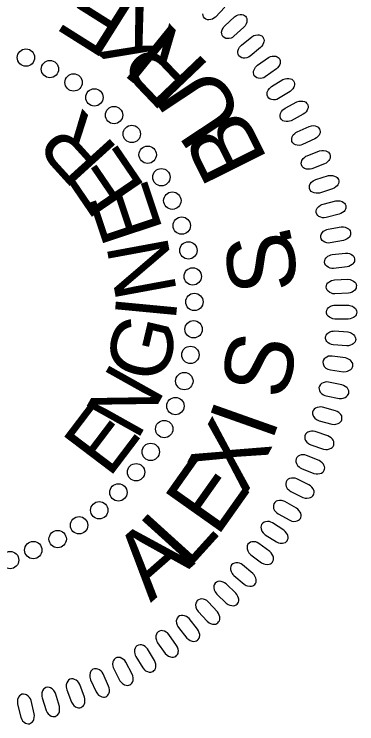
# Model space of a CAD drawing. Extents: x 474105 to 475385, y 502977 to 504774.
# Drawn here: x 474244.3 to 474275.9, y 504557.9 to 504623.4 of the extents above; entities that cross this region are included whole.
import ezdxf

# ---------------------------------------------------------------- set-up
doc = ezdxf.new("R2010")
doc.units = 0
doc.layers.add('Sheet PE Seal Cell', color=7, linetype='Continuous')

msp = doc.modelspace()

# ---------------------------------------------------------------- linework, layer by layer
at = {"layer": 'Sheet PE Seal Cell'}
msp.add_lwpolyline([(474263.704, 504624.083), (474262.838, 504623.172), (474262.704, 504623.065), (474262.575, 504622.996), (474262.4, 504622.943), (474262.223, 504622.919), (474262.097, 504622.93), (474261.943, 504622.995), (474261.821, 504623.084), (474261.741, 504623.216), (474261.7, 504623.326), (474261.677, 504623.485)], dxfattribs=at)
for points in [[(474263.705, 504622.369), (474264.609, 504623.198), (474264.796, 504623.318), (474264.933, 504623.375), (474265.134, 504623.407), (474265.281, 504623.409), (474265.416, 504623.381), (474265.516, 504623.33), (474265.606, 504623.261), (474265.667, 504623.165), (474265.726, 504623.057), (474265.753, 504622.94), (474265.75, 504622.795), (474265.732, 504622.697), (474265.667, 504622.546), (474265.575, 504622.38), (474265.473, 504622.256), (474264.552, 504621.401), (474264.412, 504621.303), (474264.278, 504621.242), (474264.1, 504621.2), (474263.922, 504621.188), (474263.797, 504621.206), (474263.647, 504621.281), (474263.531, 504621.378), (474263.46, 504621.515), (474263.426, 504621.626), (474263.413, 504621.787), (474263.457, 504621.989), (474263.544, 504622.161), (474263.619, 504622.27)], [(474265.246, 504620.589), (474266.201, 504621.36), (474266.394, 504621.469), (474266.536, 504621.516), (474266.739, 504621.535), (474266.885, 504621.529), (474267.018, 504621.492), (474267.115, 504621.436), (474267.201, 504621.36), (474267.255, 504621.261), (474267.307, 504621.149), (474267.327, 504621.03), (474267.315, 504620.886), (474267.29, 504620.789), (474267.216, 504620.643), (474267.114, 504620.483), (474267.004, 504620.366), (474266.031, 504619.571), (474265.885, 504619.481), (474265.749, 504619.429), (474265.568, 504619.398), (474265.389, 504619.397), (474265.266, 504619.423), (474265.12, 504619.507), (474265.011, 504619.612), (474264.948, 504619.753), (474264.921, 504619.865), (474264.918, 504620.027), (474264.976, 504620.226), (474265.073, 504620.392), (474265.155, 504620.496)], [(474266.724, 504618.727), (474267.726, 504619.436), (474267.926, 504619.533), (474268.07, 504619.571), (474268.273, 504619.578), (474268.419, 504619.562), (474268.549, 504619.516), (474268.642, 504619.454), (474268.723, 504619.374), (474268.771, 504619.272), (474268.816, 504619.156), (474268.828, 504619.037), (474268.807, 504618.894), (474268.777, 504618.798), (474268.694, 504618.657), (474268.582, 504618.504), (474268.465, 504618.394), (474267.444, 504617.661), (474267.293, 504617.581), (474267.152, 504617.537), (474266.971, 504617.518), (474266.792, 504617.528), (474266.67, 504617.562), (474266.531, 504617.655), (474266.428, 504617.766), (474266.375, 504617.91), (474266.354, 504618.025), (474266.362, 504618.186), (474266.431, 504618.382), (474266.539, 504618.541), (474266.627, 504618.64)], [(474268.021, 504616.76), (474269.065, 504617.405), (474269.27, 504617.489), (474269.417, 504617.518), (474269.62, 504617.512), (474269.764, 504617.487), (474269.891, 504617.433), (474269.98, 504617.366), (474270.056, 504617.28), (474270.098, 504617.175), (474270.135, 504617.057), (474270.14, 504616.937), (474270.11, 504616.795), (474270.074, 504616.702), (474269.982, 504616.567), (474269.86, 504616.421), (474269.737, 504616.318), (474268.672, 504615.651), (474268.516, 504615.581), (474268.373, 504615.546), (474268.191, 504615.538), (474268.013, 504615.56), (474267.894, 504615.601), (474267.76, 504615.702), (474267.665, 504615.82), (474267.62, 504615.968), (474267.608, 504616.083), (474267.625, 504616.243), (474267.707, 504616.434), (474267.824, 504616.586), (474267.919, 504616.679)], [(474269.264, 504614.761), (474270.346, 504615.339), (474270.557, 504615.41), (474270.705, 504615.43), (474270.908, 504615.411), (474271.05, 504615.377), (474271.173, 504615.315), (474271.258, 504615.242), (474271.329, 504615.153), (474271.363, 504615.044), (474271.393, 504614.925), (474271.39, 504614.804), (474271.351, 504614.665), (474271.309, 504614.575), (474271.209, 504614.444), (474271.079, 504614.308), (474270.949, 504614.213), (474269.844, 504613.614), (474269.684, 504613.553), (474269.54, 504613.527), (474269.357, 504613.531), (474269.181, 504613.564), (474269.065, 504613.612), (474268.938, 504613.721), (474268.85, 504613.845), (474268.814, 504613.995), (474268.81, 504614.111), (474268.837, 504614.27), (474268.93, 504614.455), (474269.057, 504614.6), (474269.157, 504614.686)], [(474270.379, 504612.582), (474271.495, 504613.091), (474271.71, 504613.148), (474271.859, 504613.159), (474272.06, 504613.128), (474272.2, 504613.084), (474272.319, 504613.015), (474272.399, 504612.937), (474272.463, 504612.842), (474272.492, 504612.733), (474272.514, 504612.612), (474272.504, 504612.492), (474272.456, 504612.355), (474272.408, 504612.267), (474272.3, 504612.144), (474272.162, 504612.015), (474272.026, 504611.928), (474270.886, 504611.4), (474270.722, 504611.35), (474270.577, 504611.333), (474270.395, 504611.348), (474270.221, 504611.392), (474270.108, 504611.448), (474269.988, 504611.566), (474269.908, 504611.693), (474269.883, 504611.845), (474269.885, 504611.962), (474269.922, 504612.119), (474270.027, 504612.297), (474270.162, 504612.434), (474270.267, 504612.515)], [(474271.308, 504610.381), (474272.454, 504610.82), (474272.672, 504610.863), (474272.821, 504610.865), (474273.02, 504610.821), (474273.157, 504610.769), (474273.272, 504610.693), (474273.346, 504610.609), (474273.404, 504610.511), (474273.426, 504610.4), (474273.441, 504610.277), (474273.423, 504610.158), (474273.366, 504610.025), (474273.314, 504609.941), (474273.198, 504609.824), (474273.051, 504609.704), (474272.91, 504609.626), (474271.74, 504609.17), (474271.573, 504609.131), (474271.427, 504609.123), (474271.245, 504609.149), (474271.075, 504609.204), (474270.966, 504609.267), (474270.854, 504609.391), (474270.782, 504609.525), (474270.766, 504609.678), (474270.775, 504609.794), (474270.822, 504609.948), (474270.939, 504610.12), (474271.082, 504610.248), (474271.192, 504610.322)], [(474272.103, 504608.172), (474273.275, 504608.537), (474273.495, 504608.567), (474273.644, 504608.559), (474273.839, 504608.503), (474273.973, 504608.442), (474274.083, 504608.359), (474274.152, 504608.271), (474274.204, 504608.17), (474274.218, 504608.057), (474274.225, 504607.934), (474274.2, 504607.816), (474274.135, 504607.687), (474274.077, 504607.606), (474273.954, 504607.497), (474273.801, 504607.386), (474273.655, 504607.317), (474272.458, 504606.936), (474272.29, 504606.907), (474272.142, 504606.908), (474271.964, 504606.946), (474271.797, 504607.011), (474271.692, 504607.08), (474271.588, 504607.212), (474271.525, 504607.35), (474271.519, 504607.504), (474271.535, 504607.619), (474271.591, 504607.77), (474271.718, 504607.934), (474271.87, 504608.053), (474271.984, 504608.119)], [(474272.775, 504605.919), (474273.967, 504606.21), (474274.189, 504606.226), (474274.337, 504606.209), (474274.529, 504606.14), (474274.658, 504606.072), (474274.762, 504605.982), (474274.826, 504605.89), (474274.872, 504605.785), (474274.879, 504605.672), (474274.879, 504605.548), (474274.845, 504605.433), (474274.773, 504605.307), (474274.71, 504605.23), (474274.58, 504605.129), (474274.42, 504605.028), (474274.271, 504604.969), (474273.052, 504604.663), (474272.882, 504604.645), (474272.735, 504604.655), (474272.559, 504604.705), (474272.397, 504604.78), (474272.296, 504604.856), (474272.201, 504604.994), (474272.146, 504605.135), (474272.15, 504605.289), (474272.173, 504605.403), (474272.239, 504605.55), (474272.376, 504605.705), (474272.535, 504605.814), (474272.653, 504605.874)], [(474273.238, 504603.591), (474274.446, 504603.807), (474274.668, 504603.809), (474274.815, 504603.782), (474275.002, 504603.701), (474275.127, 504603.625), (474275.225, 504603.528), (474275.282, 504603.433), (474275.322, 504603.326), (474275.321, 504603.212), (474275.313, 504603.089), (474275.273, 504602.976), (474275.193, 504602.855), (474275.125, 504602.782), (474274.989, 504602.69), (474274.823, 504602.599), (474274.67, 504602.549), (474273.435, 504602.32), (474273.264, 504602.312), (474273.118, 504602.332), (474272.946, 504602.393), (474272.788, 504602.478), (474272.693, 504602.56), (474272.606, 504602.704), (474272.56, 504602.848), (474272.574, 504603.002), (474272.604, 504603.113), (474272.679, 504603.256), (474272.826, 504603.404), (474272.991, 504603.502), (474273.113, 504603.554)], [(474273.63, 504601.254), (474274.849, 504601.393), (474275.07, 504601.381), (474275.216, 504601.345), (474275.397, 504601.253), (474275.517, 504601.168), (474275.609, 504601.066), (474275.66, 504600.967), (474275.693, 504600.858), (474275.686, 504600.744), (474275.67, 504600.622), (474275.623, 504600.511), (474275.535, 504600.396), (474275.462, 504600.327), (474275.321, 504600.243), (474275.15, 504600.163), (474274.994, 504600.123), (474273.747, 504599.973), (474273.576, 504599.976), (474273.432, 504600.005), (474273.263, 504600.075), (474273.112, 504600.171), (474273.021, 504600.259), (474272.944, 504600.408), (474272.907, 504600.554), (474272.93, 504600.707), (474272.967, 504600.817), (474273.051, 504600.955), (474273.206, 504601.092), (474273.378, 504601.18), (474273.503, 504601.223)], [(474273.827, 504598.908), (474275.052, 504598.97), (474275.273, 504598.944), (474275.415, 504598.899), (474275.591, 504598.796), (474275.706, 504598.705), (474275.79, 504598.597), (474275.836, 504598.494), (474275.861, 504598.382), (474275.846, 504598.27), (474275.823, 504598.149), (474275.769, 504598.042), (474275.674, 504597.932), (474275.598, 504597.868), (474275.452, 504597.793), (474275.276, 504597.724), (474275.117, 504597.694), (474273.863, 504597.622), (474273.693, 504597.636), (474273.551, 504597.673), (474273.387, 504597.755), (474273.241, 504597.859), (474273.157, 504597.953), (474273.089, 504598.106), (474273.062, 504598.255), (474273.094, 504598.406), (474273.139, 504598.512), (474273.231, 504598.645), (474273.395, 504598.773), (474273.571, 504598.85), (474273.698, 504598.885)], [(474273.895, 504596.583), (474275.122, 504596.568), (474275.341, 504596.528), (474275.48, 504596.475), (474275.649, 504596.361), (474275.757, 504596.262), (474275.836, 504596.149), (474275.874, 504596.044), (474275.892, 504595.931), (474275.871, 504595.82), (474275.84, 504595.7), (474275.779, 504595.596), (474275.678, 504595.494), (474275.597, 504595.434), (474275.447, 504595.369), (474275.267, 504595.311), (474275.107, 504595.29), (474273.851, 504595.297), (474273.682, 504595.322), (474273.542, 504595.369), (474273.384, 504595.46), (474273.245, 504595.573), (474273.167, 504595.672), (474273.109, 504595.829), (474273.091, 504595.979), (474273.132, 504596.128), (474273.183, 504596.232), (474273.284, 504596.358), (474273.455, 504596.475), (474273.636, 504596.541), (474273.766, 504596.569)], [(474273.841, 504594.195), (474275.065, 504594.103), (474275.281, 504594.05), (474275.416, 504593.988), (474275.577, 504593.863), (474275.679, 504593.758), (474275.75, 504593.64), (474275.782, 504593.533), (474275.793, 504593.42), (474275.765, 504593.31), (474275.727, 504593.192), (474275.659, 504593.092), (474275.552, 504592.996), (474275.468, 504592.942), (474275.314, 504592.886), (474275.13, 504592.839), (474274.97, 504592.829), (474273.716, 504592.915), (474273.548, 504592.95), (474273.413, 504593.006), (474273.26, 504593.106), (474273.129, 504593.229), (474273.057, 504593.332), (474273.009, 504593.492), (474273.001, 504593.644), (474273.052, 504593.789), (474273.109, 504593.89), (474273.217, 504594.009), (474273.395, 504594.115), (474273.58, 504594.17), (474273.71, 504594.189)], [(474273.461, 504590.606), (474274.676, 504590.438), (474274.898, 504590.445), (474275.044, 504590.477), (474275.228, 504590.566), (474275.349, 504590.647), (474275.443, 504590.747), (474275.498, 504590.845), (474275.533, 504590.954), (474275.528, 504591.067), (474275.514, 504591.19), (474275.47, 504591.302), (474275.385, 504591.419), (474275.315, 504591.489), (474275.176, 504591.576), (474275.006, 504591.66), (474274.851, 504591.704), (474273.607, 504591.884), (474273.436, 504591.884), (474273.292, 504591.859), (474273.121, 504591.792), (474272.968, 504591.7), (474272.875, 504591.615), (474272.794, 504591.467), (474272.755, 504591.322), (474272.774, 504591.168), (474272.809, 504591.058), (474272.89, 504590.918), (474273.042, 504590.777), (474273.211, 504590.685), (474273.334, 504590.639)], [(474273.058, 504588.212), (474274.261, 504587.968), (474274.483, 504587.961), (474274.631, 504587.984), (474274.819, 504588.06), (474274.946, 504588.134), (474275.046, 504588.228), (474275.106, 504588.322), (474275.148, 504588.428), (474275.15, 504588.542), (474275.145, 504588.666), (474275.108, 504588.78), (474275.03, 504588.902), (474274.964, 504588.977), (474274.831, 504589.073), (474274.667, 504589.167), (474274.515, 504589.221), (474273.285, 504589.478), (474273.114, 504589.489), (474272.968, 504589.472), (474272.794, 504589.417), (474272.635, 504589.335), (474272.538, 504589.255), (474272.448, 504589.113), (474272.398, 504588.971), (474272.408, 504588.816), (474272.437, 504588.704), (474272.508, 504588.559), (474272.651, 504588.409), (474272.814, 504588.307), (474272.935, 504588.252)], [(474272.414, 504585.914), (474273.599, 504585.596), (474273.821, 504585.574), (474273.969, 504585.588), (474274.162, 504585.653), (474274.293, 504585.718), (474274.399, 504585.806), (474274.465, 504585.896), (474274.514, 504586), (474274.523, 504586.113), (474274.525, 504586.236), (474274.496, 504586.353), (474274.425, 504586.48), (474274.364, 504586.558), (474274.237, 504586.662), (474274.08, 504586.766), (474273.931, 504586.83), (474272.72, 504587.163), (474272.55, 504587.186), (474272.404, 504587.178), (474272.227, 504587.134), (474272.063, 504587.062), (474271.96, 504586.988), (474271.861, 504586.853), (474271.803, 504586.713), (474271.804, 504586.559), (474271.825, 504586.445), (474271.887, 504586.296), (474272.02, 504586.136), (474272.176, 504586.025), (474272.293, 504585.963)], [(474271.656, 504583.686), (474272.818, 504583.293), (474273.037, 504583.258), (474273.186, 504583.263), (474273.383, 504583.315), (474273.518, 504583.372), (474273.629, 504583.453), (474273.701, 504583.539), (474273.756, 504583.639), (474273.772, 504583.752), (474273.783, 504583.874), (474273.759, 504583.993), (474273.698, 504584.124), (474273.642, 504584.206), (474273.522, 504584.318), (474273.371, 504584.432), (474273.227, 504584.505), (474272.039, 504584.914), (474271.87, 504584.946), (474271.724, 504584.948), (474271.544, 504584.915), (474271.376, 504584.853), (474271.269, 504584.786), (474271.163, 504584.657), (474271.096, 504584.521), (474271.086, 504584.367), (474271.1, 504584.252), (474271.153, 504584.1), (474271.275, 504583.933), (474271.425, 504583.811), (474271.537, 504583.742)], [(474270.791, 504581.513), (474271.927, 504581.049), (474272.144, 504581), (474272.293, 504580.995), (474272.492, 504581.035), (474272.631, 504581.083), (474272.747, 504581.157), (474272.824, 504581.238), (474272.885, 504581.335), (474272.908, 504581.446), (474272.926, 504581.568), (474272.911, 504581.688), (474272.858, 504581.822), (474272.807, 504581.908), (474272.694, 504582.027), (474272.55, 504582.15), (474272.411, 504582.232), (474271.251, 504582.714), (474271.086, 504582.757), (474270.939, 504582.769), (474270.758, 504582.747), (474270.586, 504582.696), (474270.475, 504582.636), (474270.36, 504582.513), (474270.286, 504582.383), (474270.266, 504582.229), (474270.272, 504582.113), (474270.316, 504581.958), (474270.428, 504581.784), (474270.569, 504581.653), (474270.677, 504581.576)], [(474269.814, 504579.37), (474270.919, 504578.835), (474271.132, 504578.773), (474271.28, 504578.759), (474271.482, 504578.785), (474271.623, 504578.825), (474271.743, 504578.891), (474271.826, 504578.968), (474271.892, 504579.06), (474271.923, 504579.17), (474271.949, 504579.291), (474271.94, 504579.411), (474271.896, 504579.548), (474271.85, 504579.637), (474271.745, 504579.763), (474271.61, 504579.895), (474271.476, 504579.985), (474270.348, 504580.54), (474270.186, 504580.593), (474270.041, 504580.614), (474269.858, 504580.603), (474269.684, 504580.563), (474269.569, 504580.51), (474269.446, 504580.395), (474269.364, 504580.269), (474269.335, 504580.117), (474269.334, 504580.001), (474269.367, 504579.844), (474269.468, 504579.662), (474269.601, 504579.523), (474269.704, 504579.44)], [(474268.627, 504577.319), (474269.696, 504576.716), (474269.905, 504576.641), (474270.052, 504576.617), (474270.255, 504576.631), (474270.399, 504576.663), (474270.523, 504576.721), (474270.609, 504576.792), (474270.682, 504576.88), (474270.72, 504576.987), (474270.752, 504577.107), (474270.752, 504577.227), (474270.716, 504577.367), (474270.677, 504577.458), (474270.579, 504577.59), (474270.452, 504577.731), (474270.325, 504577.829), (474269.234, 504578.453), (474269.075, 504578.517), (474268.931, 504578.547), (474268.749, 504578.547), (474268.572, 504578.519), (474268.455, 504578.473), (474268.325, 504578.366), (474268.234, 504578.245), (474268.196, 504578.095), (474268.188, 504577.98), (474268.211, 504577.82), (474268.301, 504577.633), (474268.424, 504577.486), (474268.522, 504577.396)], [(474267.439, 504575.39), (474268.467, 504574.72), (474268.672, 504574.633), (474268.817, 504574.6), (474269.02, 504574.601), (474269.166, 504574.623), (474269.294, 504574.673), (474269.384, 504574.739), (474269.462, 504574.823), (474269.506, 504574.927), (474269.546, 504575.044), (474269.553, 504575.164), (474269.526, 504575.307), (474269.493, 504575.4), (474269.404, 504575.538), (474269.287, 504575.686), (474269.165, 504575.792), (474268.116, 504576.484), (474267.961, 504576.558), (474267.819, 504576.595), (474267.637, 504576.608), (474267.459, 504576.59), (474267.339, 504576.552), (474267.203, 504576.453), (474267.105, 504576.339), (474267.057, 504576.192), (474267.042, 504576.076), (474267.056, 504575.916), (474267.133, 504575.723), (474267.247, 504575.568), (474267.339, 504575.473)], [(474266.112, 504573.537), (474267.096, 504572.804), (474267.294, 504572.703), (474267.437, 504572.662), (474267.64, 504572.65), (474267.787, 504572.662), (474267.918, 504572.705), (474268.011, 504572.765), (474268.095, 504572.843), (474268.145, 504572.945), (474268.193, 504573.059), (474268.208, 504573.178), (474268.19, 504573.322), (474268.162, 504573.417), (474268.082, 504573.561), (474267.974, 504573.716), (474267.859, 504573.83), (474266.855, 504574.586), (474266.706, 504574.669), (474266.567, 504574.716), (474266.386, 504574.74), (474266.207, 504574.733), (474266.085, 504574.703), (474265.943, 504574.613), (474265.838, 504574.504), (474265.781, 504574.361), (474265.758, 504574.247), (474265.762, 504574.086), (474265.827, 504573.889), (474265.931, 504573.727), (474266.017, 504573.626)], [(474264.543, 504571.61), (474265.48, 504570.816), (474265.67, 504570.703), (474265.811, 504570.653), (474266.013, 504570.629), (474266.159, 504570.632), (474266.293, 504570.666), (474266.391, 504570.72), (474266.479, 504570.793), (474266.536, 504570.892), (474266.59, 504571.002), (474266.612, 504571.12), (474266.604, 504571.265), (474266.582, 504571.362), (474266.511, 504571.51), (474266.413, 504571.672), (474266.306, 504571.792), (474265.352, 504572.61), (474265.208, 504572.703), (474265.072, 504572.758), (474264.893, 504572.793), (474264.713, 504572.798), (474264.59, 504572.775), (474264.442, 504572.694), (474264.331, 504572.593), (474264.265, 504572.453), (474264.235, 504572.341), (474264.229, 504572.179), (474264.281, 504571.979), (474264.375, 504571.811), (474264.454, 504571.705)], [(474262.957, 504569.907), (474263.841, 504569.057), (474264.025, 504568.932), (474264.162, 504568.873), (474264.362, 504568.836), (474264.508, 504568.83), (474264.643, 504568.856), (474264.745, 504568.903), (474264.837, 504568.971), (474264.9, 504569.065), (474264.961, 504569.173), (474264.991, 504569.289), (474264.991, 504569.433), (474264.975, 504569.532), (474264.914, 504569.685), (474264.826, 504569.852), (474264.727, 504569.979), (474263.826, 504570.855), (474263.688, 504570.956), (474263.556, 504571.02), (474263.379, 504571.066), (474263.201, 504571.083), (474263.076, 504571.068), (474262.924, 504570.996), (474262.806, 504570.902), (474262.732, 504570.767), (474262.695, 504570.656), (474262.678, 504570.495), (474262.718, 504570.292), (474262.801, 504570.119), (474262.873, 504570.008)], [(474261.248, 504568.298), (474262.077, 504567.394), (474262.253, 504567.258), (474262.386, 504567.189), (474262.583, 504567.141), (474262.729, 504567.126), (474262.866, 504567.143), (474262.969, 504567.184), (474263.066, 504567.245), (474263.135, 504567.336), (474263.203, 504567.439), (474263.24, 504567.554), (474263.249, 504567.698), (474263.239, 504567.797), (474263.188, 504567.953), (474263.111, 504568.125), (474263.019, 504568.258), (474262.175, 504569.189), (474262.044, 504569.299), (474261.916, 504569.371), (474261.742, 504569.428), (474261.566, 504569.456), (474261.44, 504569.449), (474261.284, 504569.387), (474261.16, 504569.3), (474261.077, 504569.17), (474261.034, 504569.062), (474261.007, 504568.903), (474261.034, 504568.697), (474261.106, 504568.519), (474261.171, 504568.404)], [(474259.431, 504566.805), (474260.203, 504565.85), (474260.369, 504565.703), (474260.497, 504565.627), (474260.692, 504565.566), (474260.836, 504565.541), (474260.973, 504565.55), (474261.08, 504565.585), (474261.18, 504565.64), (474261.254, 504565.726), (474261.328, 504565.824), (474261.372, 504565.937), (474261.391, 504566.08), (474261.387, 504566.179), (474261.346, 504566.338), (474261.279, 504566.515), (474261.197, 504566.653), (474260.413, 504567.636), (474260.289, 504567.754), (474260.165, 504567.834), (474259.996, 504567.902), (474259.821, 504567.94), (474259.695, 504567.941), (474259.535, 504567.889), (474259.407, 504567.81), (474259.315, 504567.685), (474259.266, 504567.581), (474259.229, 504567.423), (474259.243, 504567.216), (474259.304, 504567.034), (474259.362, 504566.915)], [(474257.502, 504565.419), (474258.212, 504564.418), (474258.369, 504564.261), (474258.493, 504564.177), (474258.682, 504564.103), (474258.825, 504564.07), (474258.962, 504564.07), (474259.071, 504564.098), (474259.174, 504564.147), (474259.253, 504564.228), (474259.334, 504564.322), (474259.385, 504564.431), (474259.412, 504564.573), (474259.415, 504564.673), (474259.383, 504564.833), (474259.328, 504565.014), (474259.255, 504565.158), (474258.534, 504566.187), (474258.417, 504566.313), (474258.3, 504566.4), (474258.134, 504566.478), (474257.963, 504566.527), (474257.837, 504566.537), (474257.674, 504566.494), (474257.541, 504566.424), (474257.442, 504566.305), (474257.385, 504566.204), (474257.339, 504566.049), (474257.34, 504565.842), (474257.389, 504565.656), (474257.439, 504565.533)], [(474255.487, 504564.133), (474256.132, 504563.09), (474256.28, 504562.923), (474256.397, 504562.831), (474256.582, 504562.747), (474256.723, 504562.704), (474256.86, 504562.696), (474256.97, 504562.717), (474257.076, 504562.759), (474257.16, 504562.835), (474257.246, 504562.923), (474257.304, 504563.029), (474257.34, 504563.169), (474257.35, 504563.268), (474257.328, 504563.431), (474257.284, 504563.615), (474257.22, 504563.762), (474256.565, 504564.835), (474256.456, 504564.968), (474256.345, 504565.063), (474256.185, 504565.151), (474256.016, 504565.211), (474255.891, 504565.228), (474255.726, 504565.196), (474255.588, 504565.134), (474255.483, 504565.022), (474255.42, 504564.924), (474255.364, 504564.773), (474255.352, 504564.566), (474255.389, 504564.377), (474255.432, 504564.251)], [(474253.445, 504562.993), (474254.023, 504561.911), (474254.16, 504561.735), (474254.271, 504561.636), (474254.45, 504561.54), (474254.588, 504561.489), (474254.724, 504561.472), (474254.835, 504561.486), (474254.944, 504561.521), (474255.032, 504561.591), (474255.124, 504561.674), (474255.188, 504561.776), (474255.233, 504561.914), (474255.249, 504562.012), (474255.237, 504562.176), (474255.205, 504562.362), (474255.15, 504562.514), (474254.564, 504563.625), (474254.464, 504563.765), (474254.359, 504563.866), (474254.205, 504563.965), (474254.04, 504564.035), (474253.917, 504564.06), (474253.75, 504564.038), (474253.608, 504563.985), (474253.496, 504563.88), (474253.427, 504563.786), (474253.362, 504563.639), (474253.337, 504563.433), (474253.362, 504563.242), (474253.397, 504563.114)], [(474251.309, 504561.984), (474251.818, 504560.868), (474251.943, 504560.684), (474252.048, 504560.578), (474252.221, 504560.471), (474252.355, 504560.411), (474252.49, 504560.385), (474252.602, 504560.393), (474252.712, 504560.421), (474252.805, 504560.486), (474252.902, 504560.563), (474252.972, 504560.66), (474253.026, 504560.795), (474253.048, 504560.892), (474253.047, 504561.056), (474253.026, 504561.244), (474252.981, 504561.399), (474252.466, 504562.545), (474252.375, 504562.69), (474252.276, 504562.798), (474252.128, 504562.906), (474251.968, 504562.986), (474251.847, 504563.019), (474251.679, 504563.008), (474251.534, 504562.964), (474251.415, 504562.866), (474251.341, 504562.777), (474251.267, 504562.634), (474251.228, 504562.43), (474251.241, 504562.238), (474251.268, 504562.108)], [(474249.114, 504561.074), (474249.552, 504559.928), (474249.666, 504559.737), (474249.764, 504559.624), (474249.93, 504559.506), (474250.06, 504559.438), (474250.193, 504559.404), (474250.305, 504559.405), (474250.417, 504559.426), (474250.514, 504559.484), (474250.615, 504559.555), (474250.692, 504559.648), (474250.754, 504559.779), (474250.782, 504559.875), (474250.791, 504560.038), (474250.782, 504560.228), (474250.746, 504560.385), (474250.305, 504561.561), (474250.223, 504561.712), (474250.131, 504561.825), (474249.99, 504561.943), (474249.836, 504562.033), (474249.717, 504562.073), (474249.548, 504562.073), (474249.401, 504562.038), (474249.276, 504561.947), (474249.196, 504561.863), (474249.113, 504561.725), (474249.062, 504561.524), (474249.063, 504561.332), (474249.082, 504561.2)], [(474246.843, 504560.33), (474247.209, 504559.159), (474247.31, 504558.961), (474247.401, 504558.843), (474247.559, 504558.714), (474247.684, 504558.639), (474247.815, 504558.596), (474247.927, 504558.589), (474248.04, 504558.603), (474248.14, 504558.656), (474248.246, 504558.72), (474248.328, 504558.808), (474248.398, 504558.935), (474248.432, 504559.029), (474248.451, 504559.192), (474248.455, 504559.381), (474248.429, 504559.54), (474248.061, 504560.742), (474247.989, 504560.897), (474247.905, 504561.017), (474247.772, 504561.142), (474247.623, 504561.242), (474247.507, 504561.289), (474247.339, 504561.3), (474247.19, 504561.274), (474247.06, 504561.192), (474246.974, 504561.113), (474246.883, 504560.98), (474246.82, 504560.782), (474246.809, 504560.59), (474246.819, 504560.458)], [(474244.571, 504559.734), (474244.862, 504558.542), (474244.951, 504558.338), (474245.034, 504558.214), (474245.184, 504558.076), (474245.304, 504557.993), (474245.432, 504557.942), (474245.543, 504557.928), (474245.657, 504557.935), (474245.761, 504557.981), (474245.87, 504558.039), (474245.958, 504558.121), (474246.035, 504558.244), (474246.075, 504558.336), (474246.105, 504558.496), (474246.12, 504558.685), (474246.104, 504558.845), (474245.813, 504560.068), (474245.751, 504560.227), (474245.674, 504560.352), (474245.549, 504560.486), (474245.408, 504560.595), (474245.294, 504560.649), (474245.127, 504560.67), (474244.977, 504560.654), (474244.841, 504560.58), (474244.751, 504560.506), (474244.651, 504560.379), (474244.576, 504560.187), (474244.553, 504559.996), (474244.555, 504559.863)]]:
    msp.add_lwpolyline(points, close=True, dxfattribs=at)
for centre in [(474245.346, 504619.442), (474247.554, 504618.372), (474249.74, 504617.14), (474251.663, 504615.757), (474253.477, 504614.125), (474255.12, 504612.389), (474256.582, 504610.473), (474257.85, 504608.397), (474258.86, 504606.229), (474259.726, 504603.924), (474260.349, 504601.631), (474260.744, 504599.231), (474260.893, 504596.884), (474260.822, 504594.351), (474260.531, 504591.994), (474259.967, 504589.565), (474259.148, 504587.267), (474258.108, 504585.144), (474256.865, 504583.038), (474255.517, 504581.16), (474253.886, 504579.291), (474252.11, 504577.645), (474250.253, 504576.254), (474248.273, 504574.986), (474246.024, 504573.967), (474243.885, 504573.04)]:
    msp.add_circle(centre, 0.801, dxfattribs=at)

# ---------------------------------------------------------------- texts
for s, height, rotation, p in [('E', 6.236, 147.8221, (474255.974, 504624.485)), ('K', 6.236, 140.97644, (474259.715, 504621.487)), ('R', 6.236, 133.70141, (474262.46, 504618.55)), ('U', 6.236, 123.60157, (474265.67, 504613.982)), ('R', 5.669, 132.2174, (474253.981, 504610.939)), ('B', 6.236, 116.48473, (474267.723, 504609.971)), ('E', 5.669, 124.2776, (474256.461, 504607.419)), ('E', 5.669, 108.39801, (474258.041, 504603.503)), ('.', 6.236, 102.78211, (474270.041, 504602.022)), ('S', 6.236, 95.93645, (474270.454, 504598.003)), ('N', 5.669, 100.45821, (474259.311, 504597.763)), ('I', 5.669, 84.57862, (474259.156, 504594.973)), ('G', 5.669, 76.63882, (474258.12, 504589.189)), ('S', 6.236, 77.34126, (474269.301, 504587.683)), ('N', 5.669, 60.75922, (474255.6, 504583.973)), ('E', 5.669, 52.81943, (474253.022, 504580.521)), ('I', 6.236, 70.4956, (474268.036, 504583.858)), ('X', 6.236, 61.54828, (474265.538, 504578.791)), ('E', 6.236, 54.70262, (474262.972, 504575.073)), ('L', 6.236, 47.85696, (474260.221, 504572.025)), ('A', 6.236, 41.23729, (474256.854, 504569.082))]:
    msp.add_text(s, height=height, rotation=rotation, dxfattribs=at).set_placement(p)

doc.saveas('drawing.dxf')
